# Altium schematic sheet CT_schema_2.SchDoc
size 379 x 228 mm
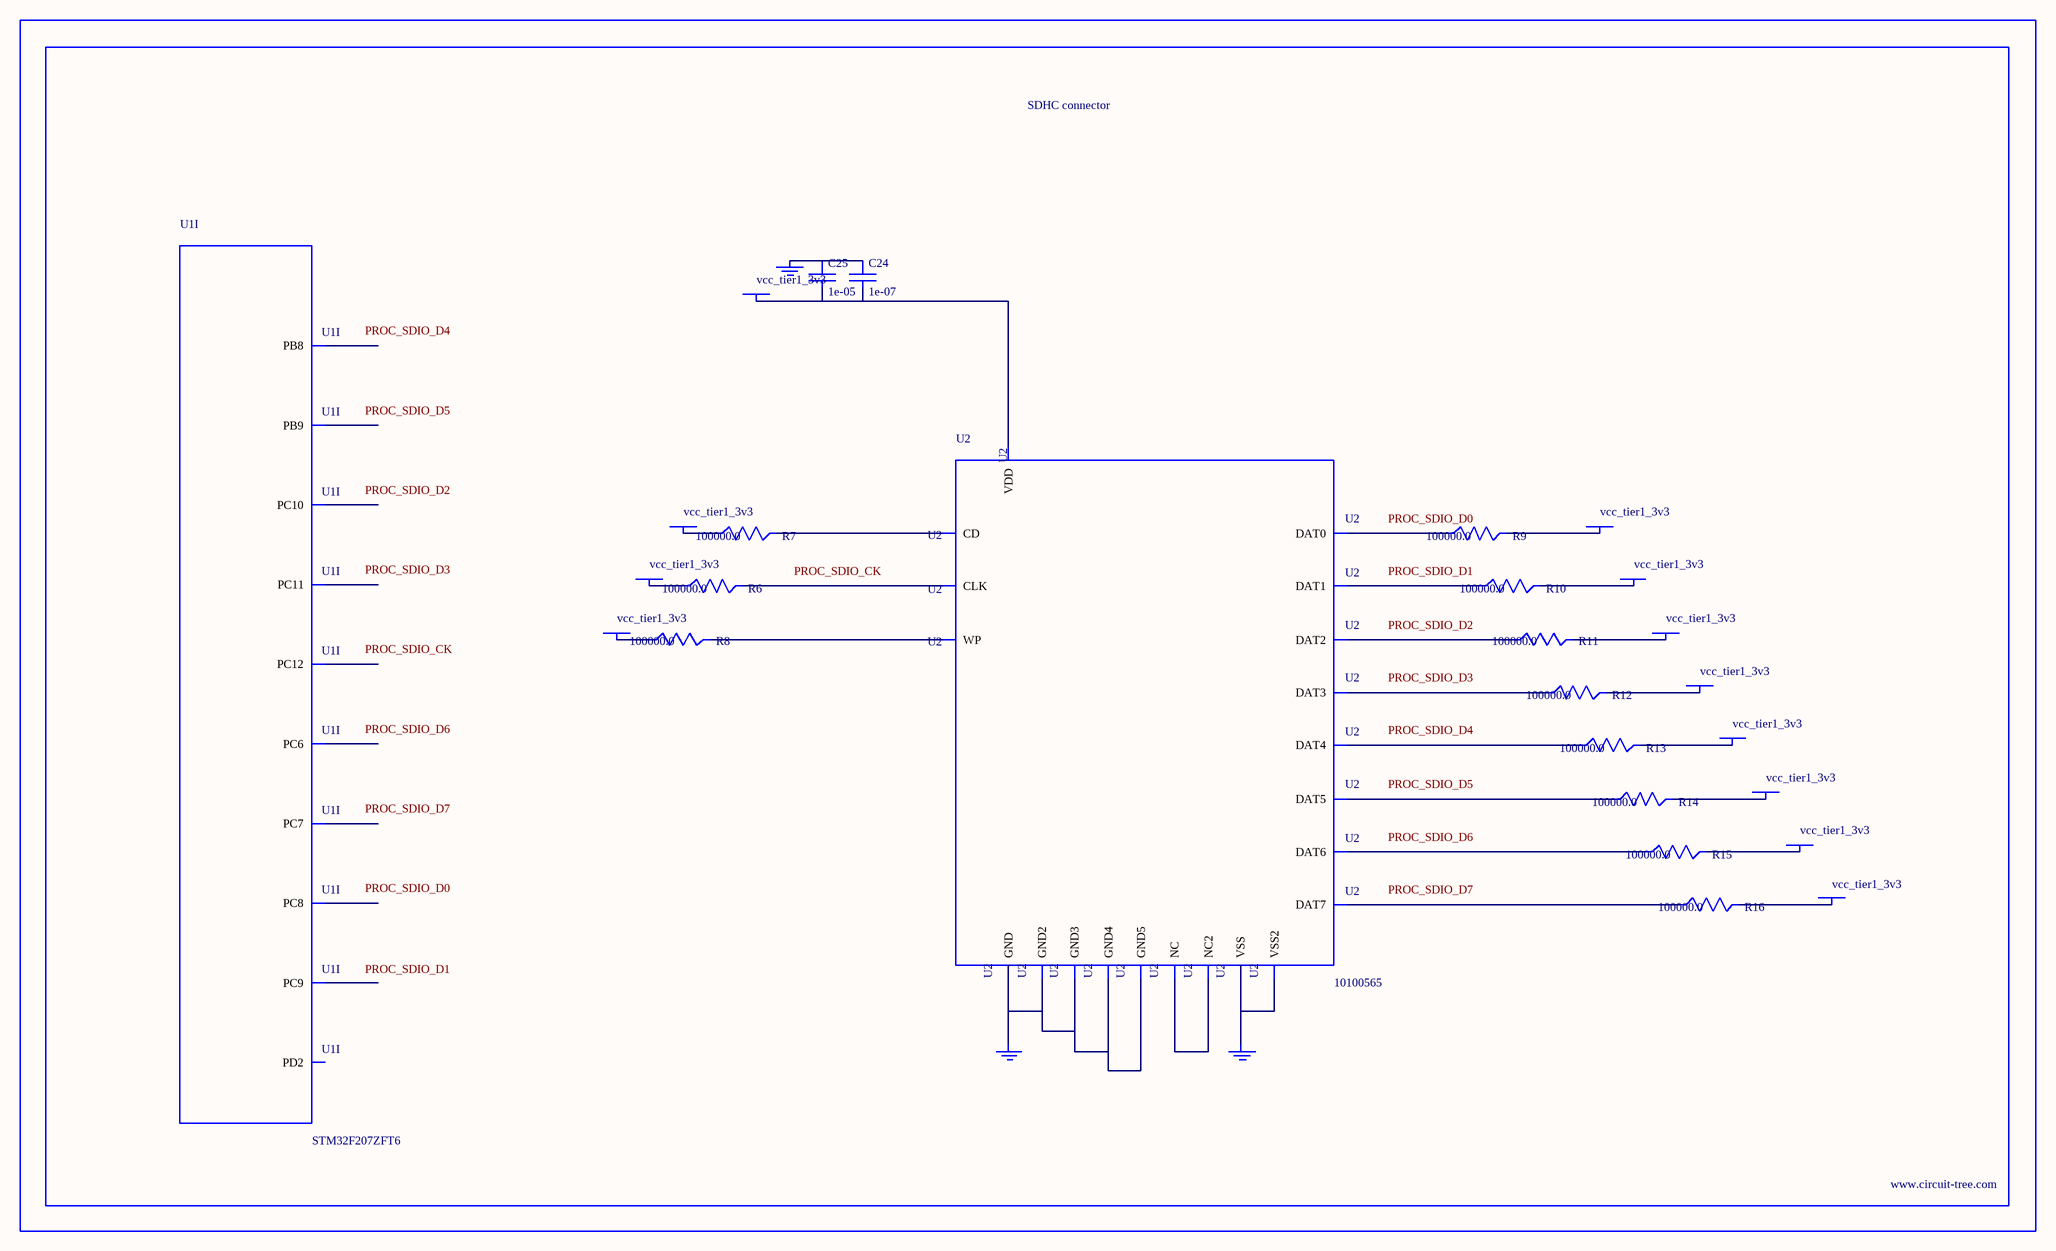
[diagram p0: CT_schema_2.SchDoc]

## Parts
BORDER1  (no value)
C24  1e-07  [C0402]
C25  1e-05  [C0805]
GND_INSTANCE_1_0  (no value)
GND_INSTANCE_1_1  (no value)
GND_INSTANCE_1_2  (no value)
POWER_INSTANCE_1_0  vcc_tier1_3v3
POWER_INSTANCE_1_1  vcc_tier1_3v3
POWER_INSTANCE_1_2  vcc_tier1_3v3
POWER_INSTANCE_1_3  vcc_tier1_3v3
POWER_INSTANCE_1_4  vcc_tier1_3v3
POWER_INSTANCE_1_5  vcc_tier1_3v3
POWER_INSTANCE_1_6  vcc_tier1_3v3
POWER_INSTANCE_1_7  vcc_tier1_3v3
POWER_INSTANCE_1_8  vcc_tier1_3v3
POWER_INSTANCE_1_9  vcc_tier1_3v3
POWER_INSTANCE_1_10  vcc_tier1_3v3
POWER_INSTANCE_1_11  vcc_tier1_3v3
R6  100000.0  [R0603]
R7  100000.0  [R0603]
R8  100000.0  [R0603]
R9  100000.0  [R0603]
R10  100000.0  [R0603]
R11  100000.0  [R0603]
R12  100000.0  [R0603]
R13  100000.0  [R0603]
R14  100000.0  [R0603]
R15  100000.0  [R0603]
R16  100000.0  [R0603]
U1  STM32F207ZFT6  [LQFP144]  (part I of 13)
U2  10100565  [10100565]

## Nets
NetC24_1: C24.1 C25.1 GND_INSTANCE_1_0.0(GND)
NetC24_2: C24.2 C25.2 POWER_INSTANCE_1_7.0(PWR) U2.9(VDD)
NetGND_INSTANCE_1_1_0: GND_INSTANCE_1_1.0(GND) U2.6(VSS) U2.10(VSS2)
NetGND_INSTANCE_1_2_0: GND_INSTANCE_1_2.0(GND) U2.12(GND) U2.16(GND2) U2.17(GND3) U2.20(GND4) U2.21(GND5)
NetPOWER_INSTANCE_1_0_0: POWER_INSTANCE_1_0.0(PWR) R8.1
NetPOWER_INSTANCE_1_1_0: POWER_INSTANCE_1_1.0(PWR) R7.1
NetPOWER_INSTANCE_1_2_0: POWER_INSTANCE_1_2.0(PWR) R10.2
NetPOWER_INSTANCE_1_3_0: POWER_INSTANCE_1_3.0(PWR) R9.2
NetPOWER_INSTANCE_1_4_0: POWER_INSTANCE_1_4.0(PWR) R16.2
NetPOWER_INSTANCE_1_5_0: POWER_INSTANCE_1_5.0(PWR) R15.2
NetPOWER_INSTANCE_1_6_0: POWER_INSTANCE_1_6.0(PWR) R6.1
NetPOWER_INSTANCE_1_8_0: POWER_INSTANCE_1_8.0(PWR) R14.2
NetPOWER_INSTANCE_1_9_0: POWER_INSTANCE_1_9.0(PWR) R13.2
NetPOWER_INSTANCE_1_10_0: POWER_INSTANCE_1_10.0(PWR) R12.2
NetPOWER_INSTANCE_1_11_0: POWER_INSTANCE_1_11.0(PWR) R11.2
NetR6_2: R6.2 U2.8(CLK)
NetR7_2: R7.2 U2.2(CD)
NetR8_2: R8.2 U2.1(WP)
NetR9_1: R9.1 U2.4(DAT0)
NetR10_1: R10.1 U2.3(DAT1)
NetR11_1: R11.1 U2.15(DAT2)
NetR12_1: R12.1 U2.14(DAT3)
NetR13_1: R13.1 U2.13(DAT4)
NetR14_1: R14.1 U2.11(DAT5)
NetR15_1: R15.1 U2.7(DAT6)
NetR16_1: R16.1 U2.5(DAT7)
NetU2_18: U2.18(NC) U2.19(NC2)

Not connected (* = marked no-connect by the designer): U1 96(PC6) 97(PC7) 98(PC8) 99(PC9) 111(PC10) 112(PC11) 113(PC12) 116(PD2) 139(PB8) 140(PB9)

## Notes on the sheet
- Labels drawn without touching a wire or pin: PROC_SDIO_CK, PROC_SDIO_D0, PROC_SDIO_D1, PROC_SDIO_D2, PROC_SDIO_D3, PROC_SDIO_D4, PROC_SDIO_D5, PROC_SDIO_D6, PROC_SDIO_D7

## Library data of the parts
BORDER1 = BORDER_PAGE1
C24 = C0402C104K3RACTU
C25 = C0805C106K8RACTU
GND_INSTANCE_1_0-GND_INSTANCE_1_2 = GND
POWER_INSTANCE_1_0-POWER_INSTANCE_1_11 = PWR
R6-R16 = RC0603JR-07100KL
